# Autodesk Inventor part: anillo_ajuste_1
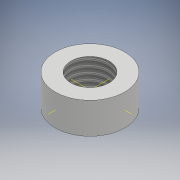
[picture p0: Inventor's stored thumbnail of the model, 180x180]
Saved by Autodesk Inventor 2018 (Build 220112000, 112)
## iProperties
Created: 2019-01
Part Number: anillo_ajuste_1
Material: Generic
Document SubType Name: Modeling
Designer: Gordillo
Density: 1 g/cm^3
Appearance: Default
Author: Gordillo
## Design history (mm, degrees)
sketch "Sketch1"
  geometry: L1 (0, -14)-(0, 14) reference; L2 (-14, 0)-(14, 0) reference; C1 r 10 at (0, 0); C2 r 5.5 at (0, 0); 1 further point
  constraints: 2 centre point, 2 coincident
  dimensions: "d0" = 20 diameter of C1; "d1" = 11 diameter of C2
extrude "Extrusion1" new body sketch "Sketch1" stored distance "d2" = 9; taper "d3" = 0 deg
thread "Thread1" dims "d4" = 10, "d5" = 0
body "Solid1"
